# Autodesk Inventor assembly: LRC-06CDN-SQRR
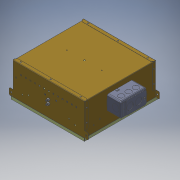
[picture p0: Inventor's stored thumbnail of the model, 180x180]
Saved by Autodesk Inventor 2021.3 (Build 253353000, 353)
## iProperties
Part Number: LRC-06CDN-SQRR
Document SubType Name: Assembly
Designer: JChurch
load_classification: Lighting
motor: 0 ul
description: 0:0:Open Appearance 6" Downlight - COB LED
manufacturer: 0:0:The Kirlin Company
model: 0:0:LRC-06CDN
url: 0:0:
Author: JChurch
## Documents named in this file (6)
- X:\Revit Files\0000-Un-Zipped\COB\LRC-06CDN-SQR\LRC-06CDN-SQRR.iam
- X:\INVENTOR\830\830376-01-00.iam
- X:\INVENTOR\881\881088-00-00.iam
- X:\INVENTOR\700\700466-00-XX.iam
- X:\INVENTOR\725\725267-00-00.ipt
- X:\Revit Files\0000-Un-Zipped\COB\LRC-06CDN-SQR\LRC-06CDN-SQRR_Substitute_1.ipt
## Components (5 placed, 5 different names)
1. 830376-01-00:1 [sub-assembly] — Mate:1, Mate:2, Flush:1, Tangent:1, Mate:8
2. 881088-00-00:1 [sub-assembly] — Tangent:1, Mate:3, Mate:4
3. 700466-00-XX:1 [sub-assembly] — Mate:5, Mate:6, Mate:7, Mate:8, Mate:9, Mate:10
4. 725267-00-00:1 — Mate:5, Mate:6, Mate:7
5. LRC-06CDN-SQRR_Substitute_1:1
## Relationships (12: Mate 10, Flush 1, Tangent 1)
- Mate:1: 830376-01-00:1
- Mate:2: 830376-01-00:1
- Flush:1: 830376-01-00:1
- Tangent:1: 830376-01-00:1 ↔ 881088-00-00:1
- Mate:3: 881088-00-00:1
- Mate:4: 881088-00-00:1
- Mate:5: 700466-00-XX:1 ↔ 725267-00-00:1
- Mate:6: 700466-00-XX:1 ↔ 725267-00-00:1
- Mate:7: 700466-00-XX:1 ↔ 725267-00-00:1
- Mate:8: 830376-01-00:1 ↔ 700466-00-XX:1
- Mate:9: 700466-00-XX:1
- Mate:10: 700466-00-XX:1
